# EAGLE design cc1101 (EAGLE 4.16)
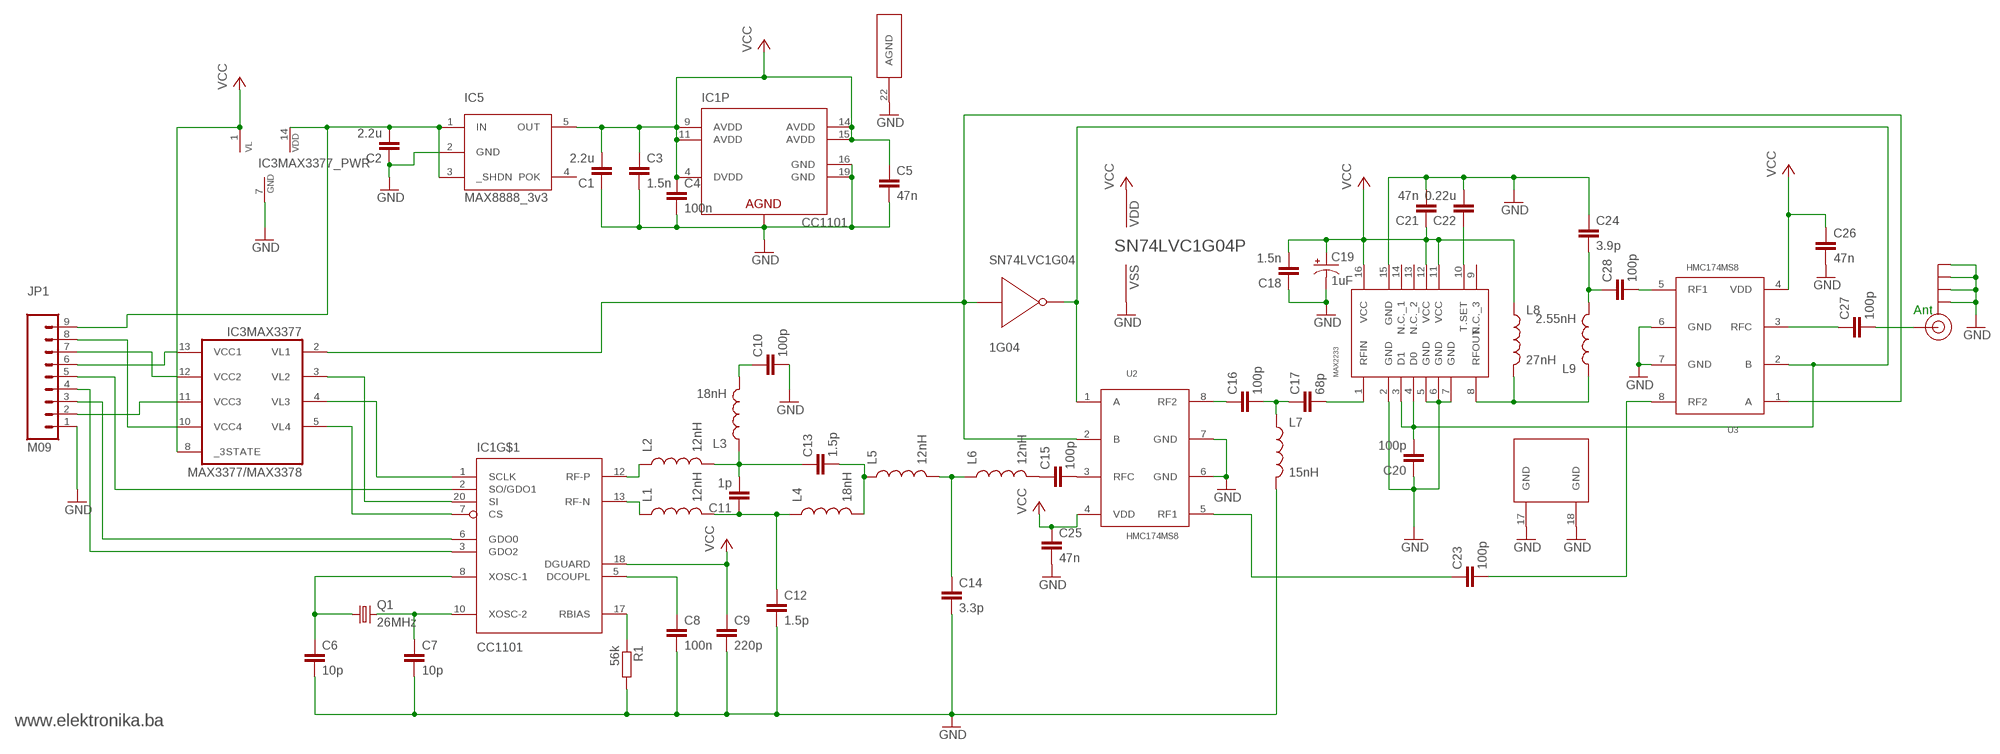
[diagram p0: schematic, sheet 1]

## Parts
C1  2.2u  C-EUC0603  [C0603]
C2  2.2u  C-EUC0603  [C0603]
C3  1.5n  C-EUC0603  [C0603]
C4  100n  C-EUC0603  [C0603]
C5  47n  C-EUC0603  [C0603]
C6  10p  C-EUC0603  [C0603]
C7  10p  C-EUC0603  [C0603]
C8  100n  C-EUC0603  [C0603]
C9  220p  C-EUC0603  [C0603]
C10  100p  C-EUC0603  [C0603]
C11  1p  C-EUC0603  [C0603]
C12  1.5p  C-EUC0603  [C0603]
C13  1.5p  C-EUC0603  [C0603]
C14  3.3p  C-EUC0603  [C0603]
C15  100p  C-EUC0603  [C0603]
C16  100p  C-EUC0603  [C0603]
C17  68p  C-EUC0603  [C0603]
C18  1.5n  C-EUC0603  [C0603]
C19  1uF  CAP_POL1206  [EIA3216]
C20  100p  C-EUC0603  [C0603]
C21  47n  C-EUC0603  [C0603]
C22  0.22u  C-EUC0603  [C0603]
C23  100p  C-EUC0603  [C0603]
C24  3.9p  C-EUC0603  [C0603]
C25  47n  C-EUC0603  [C0603]
C26  47n  C-EUC0603  [C0603]
C27  100p  C-EUC0603  [C0603]
C28  100p  C-EUC0603  [C0603]
IC1  CC1101  CC1100QLP-20-NEW  [QLP-20-NEW]
IC3  MAX3377/MAX3378  MAX3377  [TSSOP14]
IC5  MAX8888_3v3  MAX8888  [SOT23-5]
JP1  M09  [1X09]
L1  12nH  INDUCTOR0603  [0603]
L2  12nH  INDUCTOR0603  [0603]
L3  18nH  INDUCTOR0603  [0603]
L4  18nH  INDUCTOR0603  [0603]
L5  12nH  INDUCTOR0603  [0603]
L6  12nH  INDUCTOR0603  [0603]
L7  15nH  INDUCTOR0603  [0603]
L8  27nH  INDUCTOR0603  [0603]
L9  2.55nH  INDUCTOR0603  [0603]
Q1  26MHz  CRYSTAL5X3  [CRYSTAL-SMD-5X3]
R1  56k  R-EU_R0603  [R0603]
SMA1  SMA_EDGE  [SMA-EDGE]
SN74LVC1G04  1G04  [SOT23-5]
U2  HMC174MS8  [MSOP8]
U3  HMC174MS8  [MSOP8]
U$1  MAX2233TSSOP  MAX2233TSSOP16  [TSSOP16]

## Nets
DCOUPL: C8.1 IC1.5(DCOUPL)
GND: C1.1 C2.1 C3.2 C4.2 C5.2 C6.2 C7.2 C8.2 C9.2 C10.2 C12.2 C14.2 C18.1 C19.C(-) C20.1 C21.2 C22.2 C24.1 C25.2 C26.2 IC1.16(P:GND) IC1.19(P:GND) IC1.21(P:AGND) IC1.22(AGND) IC3.7(MAX3377_PWR:GND) IC5.2(GND) JP1.1 L7.2 R1.2 SMA1.GND@0(GND) SMA1.GND@1(GND) SMA1.GND@2(GND) SMA1.GND@3(GND) SN74LVC1G04.3(VSS) U2.6(GND) U2.7(GND) U3.6(GND) U3.7(GND) U$1.2(GND) U$1.5(GND) U$1.6(GND) U$1.7(GND) U$1.15(GND) U$1.17(GND) U$1.18(GND)
L8: IC1.12(RF-P) L2.1
N$1: IC1.17(RBIAS) R1.1
N$2: C15.1 L6.2
N$3: IC1.13(RF-N) L1.1
N$4: C10.1 L3.2
N$5: IC3.13(MAX3377:VCC1) JP1.6
N$6: C6.1 IC1.8(XOSC-1) Q1.1
N$7: C15.2 U2.3(RFC)
N$8: L8.2 L9.1 U$1.8(RFOUT)
N$9: C13.2 L4.2 L5.1
N$10: C7.1 IC1.10(XOSC-2) Q1.3
N$11: C16.1 U2.8(RF2)
N$12: C28.2 U3.5(RF1)
N$13: C27.1 U3.3(RFC)
N$14: C17.2 U$1.1(RFIN)
N$15: C20.2 SN74LVC1G04.4(Q) U2.1(A) U3.2(B) U$1.3(D1) U$1.4(D0)
N$16: C11.2 C13.1 L2.2 L3.1
N$18: C27.2 SMA1.SIG(SIGNAL)
N$19: C22.1 U$1.10(T.SET)
N$20: C24.2 C28.1 L9.2
N$21: C16.2 C17.1 L7.1
N$22: IC1.2(SO/GDO1) JP1.5
N$23: IC1.1(SCLK) IC3.4(MAX3377:VL3)
N$24: IC1.20(SI) IC3.3(MAX3377:VL2)
N$25: IC1.7(CS) IC3.5(MAX3377:VL4)
N$26: IC1.6(GDO0) JP1.3
N$27: IC1.3(GDO2) JP1.4
N$28: IC3.12(MAX3377:VCC2) JP1.7
N$29: C2.2 IC3.14(MAX3377_PWR:VDD) IC5.1(IN) IC5.3(_SHDN) JP1.9
N$30: C23.1 U2.5(RF1)
N$31: IC3.11(MAX3377:VCC3) JP1.2
N$32: C23.2 U3.8(RF2)
N$33: C11.1 C12.1 L1.2 L4.1
N$34: C14.1 L5.2 L6.1
N$36: IC3.10(MAX3377:VCC4) JP1.8
N$47: IC3.2(MAX3377:VL1) SN74LVC1G04.2(A) U2.2(B) U3.1(A)
VCC: C1.2 C3.1 C4.1 C5.1 C9.1 C18.2 C19.A(+) C21.1 C25.1 C26.1 IC1.4(P:DVDD) IC1.9(P:AVDD) IC1.11(P:AVDD) IC1.14(P:AVDD) IC1.15(P:AVDD) IC1.18(DGUARD) IC3.1(MAX3377_PWR:VL) IC3.8(MAX3377:_3STATE) IC5.5(OUT) L8.1 SN74LVC1G04.5(VDD) U2.4(VDD) U3.4(VDD) U$1.11(VCC) U$1.12(VCC) U$1.16(VCC)
Unconnected: IC5.4(POK) U$1.9(N.C._3) U$1.13(N.C._2) U$1.14(N.C._1)

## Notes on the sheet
- Ant
- www.elektronika.ba

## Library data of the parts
C1-C18 C20-C28 = rcl:C-EU: CAPACITOR, European symbol
C19 = SparkFun:CAP_POL: Capacitor Polarized
IC1 = chipcon-ti:CC1100: Single Chip Low Cost Low Power RF Transceiver 315/433/868 and 915 MHz ISM/SRD band systems
IC3 = MAX3377:MAX3377: Micropower PLL
IC5 = MAX3377:MAX8888
JP1 = SparkFun:M09: Header 9 Standard 9-pin 0.1" header. Use with straight break away headers (SKU : PRT-00116), right angle break away headers (PRT-00553), swiss pins (PRT-00743), machine pins (PRT-00117), and female headers (PRT-00115).
L1-L9 = SparkFun:INDUCTOR: Inductors
Q1 = SparkFun:CRYSTAL: Crystals
R1 = rcl:R-EU_: RESISTOR, European symbol
SMA1 = SparkFun:SMA_EDGE: SMA Antenna Connector End launch SMA connector. The paste layer has been removed so that the connector can be hand soldered onto the board after reflow.
SN74LVC1G04 = little-logic:1G04: NOT
U2 U3 = trax:HMC174MS8
U$1 = trax:MAX2233

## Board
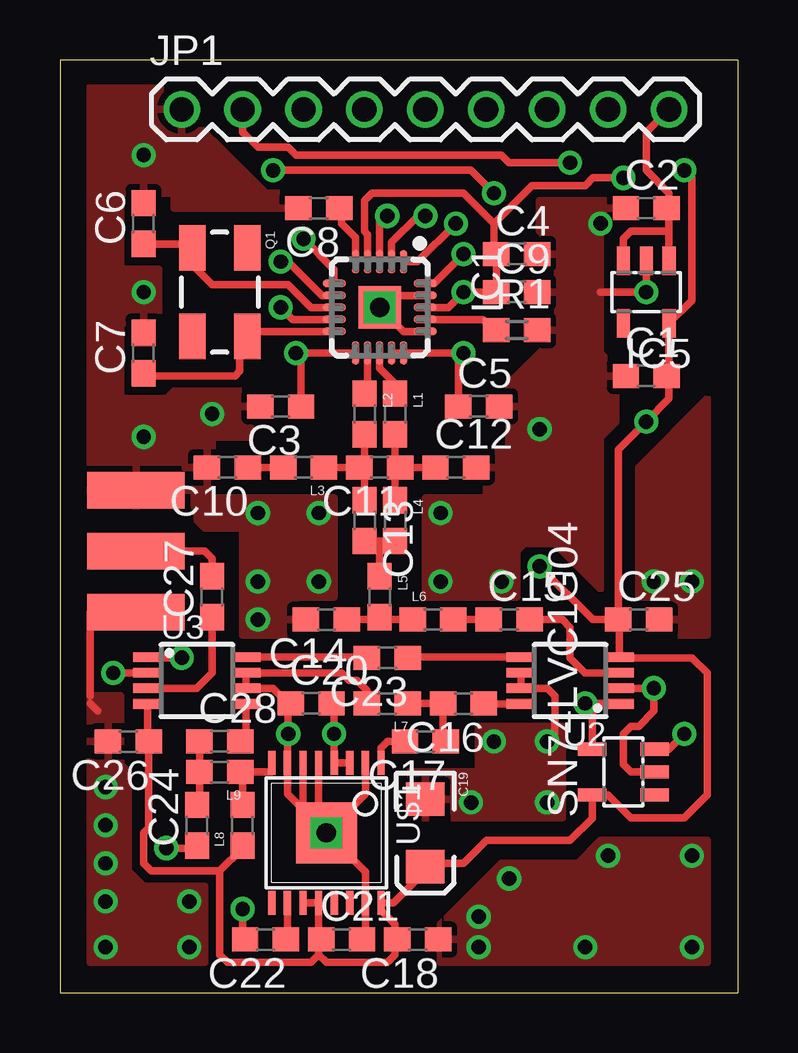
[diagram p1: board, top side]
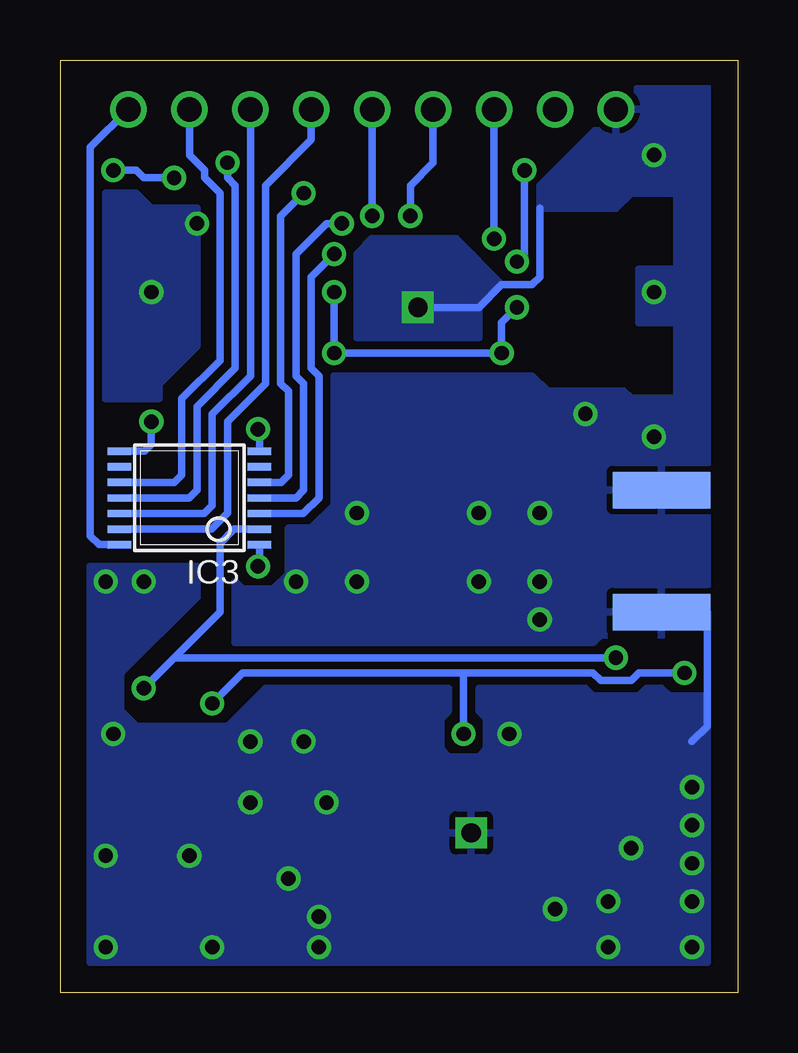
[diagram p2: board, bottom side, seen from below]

Size 28.25 x 38.88 mm. Coordinates in mm from the lower left corner, seen from the top.
Outline: 28.25,38.88 0,38.88 0,0 28.25,0 28.25,38.88
Copper layers (1*16): Top 0.035mm / dielectric 1.5mm / Bottom 0.035mm
Design rules "default": minimum track width 10mil, minimum drill 24mil, track to track 8mil, track to pad 8mil, pad to pad 8mil, via to via 8mil, smd to smd 8mil, copper to edge 40mil, drill to drill 8mil, minimum pad ring 10mil, minimum via ring 8mil, stop-mask expansion 4mil, vias tented up to drill 0mil, thermal gap 10mil

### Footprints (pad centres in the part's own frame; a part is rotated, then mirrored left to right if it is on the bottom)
C0603 = smd 1.1 x 1: 1 -0.85,0; 2 0.85,0
EIA3216 = smd 1.4 x 1.6: A 1.4,0; C -1.4,0
QLP-20-NEW = smd 0.95 x 0.3: 1 -1.9,1; 2 -1.9,0.5; 3 -1.9,0; 4 -1.9,-0.5; 5 -1.9,-1; 11 1.9,-1; 12 1.9,-0.5; 13 1.9,0; 14 1.9,0.5; 15 1.9,1 | smd 0.3 x 0.95: 6 -1,-1.9; 7 -0.5,-1.9; 8 0,-1.9; 9 0.5,-1.9; 10 1,-1.9; 16 1,1.9; 17 0.5,1.9; 18 0,1.9; 19 -0.5,1.9; 20 -1,1.9 | drill 0.8 square: 21 0,0 | smd 1.778 x 1.778: 22 0,0
TSSOP14 = smd 0.305 x 0.991: 1 -2.275,-2.918; 2 -1.625,-2.918; 3 -0.975,-2.918; 4 -0.325,-2.918; 5 0.325,-2.918; 6 0.975,-2.918; 7 1.625,-2.918; 8 1.625,2.918; 9 0.975,2.918; 10 0.325,2.918; 11 -0.325,2.918; 12 -0.975,2.918; 13 -1.625,2.918; 14 -2.275,2.918
SOT23-5 = smd 0.55 x 1.2: 1 -0.95,-1.3; 2 0,-1.3; 3 0.95,-1.3; 4 0.95,1.3; 5 -0.95,1.3
1X09 = drill 1.016 round: 1 0,0; 2 2.54,0; 3 5.08,0; 4 7.62,0; 5 10.16,0; 6 12.7,0; 7 15.24,0; 8 17.78,0; 9 20.32,0
0603 = smd 1.1 x 1: 1 -0.85,0; 2 0.85,0
CRYSTAL-SMD-5X3 = smd 1.9 x 1.1: 1 -1.85,-1.15; 2 1.85,-1.15; 3 1.85,1.15; 4 -1.85,1.15
R0603 = smd 1.1 x 1: 1 -0.85,0; 2 0.85,0
SMA-EDGE = smd 1.524 x 4.064: GND@0 0,0; GND@1 5.08,0; SIG 2.54,0 | smd 1.524 x 4.064 bottom: GND@2 0,0; GND@3 5.08,0
MSOP8 = smd 0.4 x 1.2: 1 -0.975,-2.05; 2 -0.325,-2.05; 3 0.325,-2.05; 4 0.975,-2.05; 5 0.975,2.05; 6 0.325,2.05; 7 -0.325,2.05; 8 -0.975,2.05
TSSOP16 = smd 0.305 x 0.991: 1 -2.275,-2.918; 2 -1.625,-2.918; 3 -0.975,-2.918; 4 -0.325,-2.918; 5 0.325,-2.918; 6 0.975,-2.918; 7 1.625,-2.918; 8 2.275,-2.918; 9 2.275,2.918; 10 1.625,2.918; 11 0.975,2.918; 12 0.325,2.918; 13 -0.325,2.918; 14 -0.975,2.918; 15 -1.625,2.918; 16 -2.275,2.918 | smd 2.54 x 2.54: 17 0,0 | drill 0.8 square: 18 0,0

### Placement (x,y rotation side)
C1  24.44,25.71 0 top
C2  24.44,32.7 0 top
C3  9.2,24.44 180 top
C4  19.05,30.79 0 top
C5  17.46,24.44 0 top
C6  3.49,32.06 90 top
C7  3.49,26.66 90 top
C8  10.79,32.7 180 top
C9  19.05,29.2 0 top
C10  6.98,21.9 180 top
C11  13.33,21.9 180 top
C12  16.51,21.9 0 top
C13  12.69,19.68 270 top
C14  11.11,15.55 180 top
C15  18.73,15.55 0 top
C16  16.82,12.06 180 top
C17  15.23,10.47 180 top
C18  14.92,2.22 180 top
C19  15.23,6.66 270 top
C20  10.47,12.06 0 top
C21  11.74,2.22 0 top
C22  8.57,2.22 180 top
C23  13.65,13.96 180 top
C24  5.71,6.98 90 top
C25  24.12,15.55 0 top
C26  2.85,10.47 180 top
C27  6.34,16.5 90 top
C28  6.66,10.47 0 top
IC1  13.33,28.57 270 top
IC3  22.86,20.95 90 bottom
IC5  24.44,29.2 180 top
JP1  5.08,36.82 0 top
L1  13.96,24.12 270 top
L2  12.69,24.12 270 top
L3  10.15,21.9 180 top
L4  13.96,19.68 270 top
L5  13.33,16.5 270 top
L6  15.55,15.55 0 top
L7  13.65,12.06 180 top
L8  7.62,6.98 90 top
L9  6.66,9.2 180 top
Q1  6.66,29.2 270 top
R1  19.05,27.62 0 top
SMA1  3.17,20.95 270 top
SN74LVC1G04  23.49,9.2 90 top
U2  21.27,13.01 90 top
U3  5.71,13.01 270 top
U$1  11.11,6.66 180 top
U$2  [ELEBALOGO_B_122]  15.87,20.63 0 bottom

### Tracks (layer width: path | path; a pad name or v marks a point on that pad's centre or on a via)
DCOUPL
  Top 0.305: IC1.5 12.33,31.47 11.74,32.06 11.74,32.7 C8.1
GND  (via drill 0.6)
  Top 0.305: C9.2 20,29.2 19.89,29.31 | 20,27.62 19.89,27.72 | U3.6 | U3.6 U3.7 7.62,13.34 7.62,13.33 11.74,13.33 12.06,13.01 12.38,13.01 12.8,12.59 L7.2 | U2.7 | U2.7 U2.6 | U2.7 19.05,12.69 | U3.6 8.88,12.69 9.52,12.06 | 9.52,12.06 C20.1 | 1.58,11.74 1.27,12.06 | 1.27,12.38 1.27,15.87 SMA1.GND@1 | IC5.2 v24.44,29.2 22.54,29.2 | 9.52,12.06 v9.52,10.79 9.48,10.79 U$1.7 9.48,8.29 10.15,7.61 | 10.79,7.61 10.78,7.61 | C24.1 5.71,6.03 v4.44,6.03 | C22.2 arc-90 7.62,2.32 v7.62,3.49 | C21.2 12.69,2.22 arc90 12.73,2.25 | 12.73,2.25 U$1.15 | U2.7 20.32,12.69 20.63,12.38 20.63,10.79 v20.32,10.47 | SN74LVC1G04.3 25.39,10.15 v26.03,10.79 | U$1.18 11.11,7.3 10.79,7.61 | 10.79,7.61 10.15,7.61 | 10.15,7.61 10.13,7.61 | U$1.6 10.13,7.64 10.15,7.61 | U$1.5 10.78,7.62 10.79,7.61 | U$1.2 12.73,8.29 U$1.18 | 12.73,2.25 12.73,5.04 U$1.18 | IC1.16 14.33,27.57 IC1.22 13.83,29.07 IC1.19
  Top 0.406: R1.2 20,27.62
  Bottom 0.305: SMA1.GND@1 1.27,15.87 1.27,11.11 1.9,10.47 | IC3.7 19.94,23.43 v20,23.49 | IC1.22 10.79,28.57 9.84,29.52 8.57,29.52 8.25,29.84 8.25,32.7
  other vias: 3.49,29.2 6.34,24.12 10.79,20 10.79,17.14 8.25,20 8.25,17.14 8.25,15.55 3.49,34.92 20.32,7.93 5.39,1.9 1.9,1.9 5.39,3.8 1.9,8.57 15.87,20 15.87,17.14 18.41,17.14 3.49,23.17 24.76,17.14 26.35,17.14 22.86,5.71 26.35,5.71 21.9,1.9 26.35,1.9 17.46,1.9 17.14,7.93 18.09,10.47 18.73,4.76 1.9,5.39 1.9,3.8 1.9,6.98 22.54,32.06 17.46,3.17
  pour Top: 1.27,37.78 1.27,20.31 5.71,20.31 5.71,19.68 6.03,19.36 7.62,19.36 7.62,14.92 9.84,14.92 9.84,16.5 11.42,16.5 11.42,20.63 6.34,20.63 6.34,23.17 7.93,23.17 7.93,25.08 4.76,25.08 4.44,24.76 2.54,24.76 2.54,27.93 4.12,27.93 4.12,30.16 2.54,30.16 2.54,33.33 4.76,33.33 4.76,32.7 9.52,32.7 9.52,33.33 8.57,33.33 4.12,37.78
  pour Bottom (no thermals): 15.87,30.79 15.23,31.43 11.74,31.43 9.84,29.52 10.79,28.57 10.79,27.3 15.87,27.3
  pour Bottom: 1.27,37.78 4.12,37.78 8.25,33.65 8.25,32.7 5.08,32.7 4.44,33.33 2.54,33.33 2.54,30.16 4.12,30.16 4.12,27.93 2.54,27.93 2.54,24.76 4.44,24.76 4.76,25.08 7.93,25.08 8.57,25.71 16.82,25.71 16.82,20.31 17.78,19.36 18.73,19.36 18.73,17.46 19.36,16.82 20.63,16.82 20.95,17.14 20.95,14.6 6.03,14.6 5.71,14.92 1.27,14.92
  pour Bottom: 1.27,1.26 26.98,1.26 26.98,17.77 22.54,17.77 22.54,16.5 25.71,13.33 25.71,11.74 25.08,11.11 21.27,11.11 19.68,12.69 12.06,12.69 12.06,11.74 12.38,11.42 12.38,10.15 12.06,9.84 10.79,9.84 10.47,10.15 10.47,11.42 10.79,11.74 10.79,12.69 6.34,12.69 6.03,12.38 4.12,12.38 3.81,12.69 3.17,12.69 2.85,12.38 1.27,12.38
  pour Top: 17.46,11.11 17.46,9.2 14.6,9.2 14.6,7.3 20.95,7.3 20.95,11.11
  pour Top: 6.03,1.26 6.03,4.44 3.49,4.44 2.85,5.07 2.85,9.2 2.54,9.52 2.54,12.38 1.27,12.38 1.27,1.26
  pour Top: 20,33.01 23.17,33.01 23.17,32.38 22.54,31.74 22.54,26.66 23.17,26.03 23.17,23.81 22.54,23.17 22.54,16.82 20.63,18.73 19.36,18.73 19.05,18.41 19.05,16.5 15.23,16.5 15.23,20.63 17.78,20.63 17.78,22.54 18.73,22.54 18.73,25.39 20.32,26.98 20.32,31.43 20,31.74
  pour Top: 24.12,21.9 26.98,24.76 26.98,14.92 25.39,14.92 25.39,16.5 24.12,16.5
  pour Top: 26.98,1.26 26.98,6.34 22.54,6.34 21.59,5.39 18.41,5.39 15.87,2.85 15.87,1.26
  pour Bottom: 22.54,32.7 24.44,32.7 25.08,33.33 26.35,33.33 26.35,24.76 24.12,24.76 24.12,25.39 22.54,26.98
L8
  Top 0.305: L2.1 12.69,25.08 12.83,25.21 IC1.12
N$1
  Top 0.305: R1.1 18.09,27.62 17.64,28.07 IC1.17
N$2
  Top 0.305: L6.2 C15.1
N$3
  Top 0.305: L1.1 13.96,25.39 13.33,26.03 IC1.13
N$4
  Top 0.305: L3.2 C10.1
N$5
  Bottom 0.305: IC3.13 21.94,19.32 21.27,20 21.27,23.81 19.68,25.39 19.68,33.65 17.78,35.55 JP1.6
N$6
  Top 0.305: IC1.8 10.47,28.57 9.52,29.52 6.34,29.52 5.39,30.47 5.39,31.11 | 5.39,31.11 5.39,31.05 Q1.1 | C6.1 5.39,31.21 5.39,31.11
N$7
  Top 0.305: U2.3 21.89,13.34 21.27,13.96 21.27,15.23 20.95,15.55 C15.2
N$8
  Top 0.305: U$1.8 8.83,9.2 7.62,9.2 | L9.1 7.62,9.2 | 7.62,9.2 L8.2
N$9
  Top 0.305: C13.2 12.69,18.73 12.8,18.83 13.33,18.83 | 13.33,18.83 L4.2 | L5.1 13.33,18.83
N$10
  Top 0.305: 7.5,27.5 7.62,27.62 7.66,27.57 IC1.10 | 7.5,27.5 Q1.3 | 7.5,27.5 7.5,25.91 7.3,25.71 3.49,25.71 C7.1
N$11
  Top 0.305: C16.1 17.78,12.06 17.8,12.04 U2.8
N$12
  Top 0.305: U3.5 7.76,10.47 C28.2
N$13
  Top 0.305: U3.3 5.7,12.69 6.34,13.33 C27.1
N$14
  Top 0.305: U$1.1 13.38,10.21 13.65,10.47 C17.2
N$15  (via drill 0.6)
  Top 0.305: U3.2 v2.22,13.34 v2.22,13.33 | U2.1 23.3,12.06 v21.9,12.06 22.19,11.77 SN74LVC1G04.4 | C20.2 11.42,12.06 v11.42,10.79 v11.43,10.78 U$1.4 12.06,9.58 | 12.06,9.58 U$1.3 | 12.06,9.58 12.06,9.52
  Bottom 0.305: v21.9,12.06 20.63,13.33 11.42,13.33 | v2.22,13.33 4.12,13.33 4.44,13.01 5.71,13.01 6.03,13.33 11.42,13.33 | 11.42,13.33 v11.42,10.79
N$16
  Top 0.305: 12.69,21.9 L2.2 | 12.69,21.9 C13.1 | 12.69,21.9 C11.2 | L3.1 12.69,21.9
N$18
  Top 0.305: C27.2 6.34,18.09 6.03,18.41 SMA1.SIG
N$19
  Top 0.305: C22.1 9.52,2.22 9.48,2.25 U$1.10
N$20
  Top 0.305: 5.71,10.47 C28.1 L9.2 5.81,7.61 5.71,7.61 C24.2
N$21
  Top 0.305: 15.87,12.06 C16.2 | 15.87,12.06 15.97,11.96 15.97,10.69 16.19,10.47 C17.1 | L7.1 15.87,12.06
N$22  (via drill 0.6)
  Top 0.305: IC1.2 13.83,31.29 14.92,32.38 v15.23,32.38
  Bottom 0.305: v15.23,32.38 JP1.5
N$23  (via drill 0.6)
  Top 0.305: IC1.1 14.91,30.47 v16.51,32.06
  Bottom 0.305: IC3.4 18.42,20.62 18.09,20.95 18.09,25.39 18.41,25.71 18.41,30.79 17.14,32.06 v16.51,32.06
N$24  (via drill 0.6)
  Top 0.305: IC1.20 15.6,29.57 v16.82,30.79
  Bottom 0.305: IC3.3 18.12,19.97 17.46,20.63 17.46,25.71 17.78,26.03 17.78,29.84 v16.82,30.79
N$25  (via drill 0.6)
  Top 0.305: IC1.7 10.92,29.07 9.52,30.47 v9.2,30.47 | v8.88,34.28 17.14,34.28 v18.09,33.33
  Bottom 0.305: v9.2,30.47 8.88,30.79 v8.88,34.28 | IC3.5 19.04,21.27 18.73,21.58 18.73,25.08 19.05,25.39 19.05,32.38 v18.09,33.33
N$26  (via drill 0.6)
  Top 0.305: IC1.6 11.43,30.15 v10.15,31.43
  Bottom 0.305: v10.15,31.43 JP1.3
N$27  (via drill 0.6)
  Top 0.305: IC1.3 13.33,32.06 v13.65,32.38
  Bottom 0.305: v13.65,32.38 13.65,33.65 12.69,34.6 JP1.4
N$28
  Bottom 0.305: IC3.12 22.24,19.97 21.9,20.31 21.9,24.12 20.32,25.71 JP1.7
N$29
  Top 0.305: IC5.3 23.49,31.43 23.81,31.74 25.39,31.74 | 25.39,31.74 25.39,32.7 25.39,33.33 24.44,34.28 24.44,35.87 JP1.9 | IC5.1 25.39,31.74
  Top 0.406: 25.39,32.7 C2.2
  Bottom 0.305: IC3.14 26.61,18.67 26.98,19.04 26.98,35.24 JP1.9
N$30
  Top 0.305: C23.1 14.28,13.96 14.28,13.99 U2.5
N$31  (via drill 0.6)
  Top 0.305: JP1.2 7.62,35.87 8.25,35.24 9.52,35.24 9.84,34.92 18.41,34.92 18.73,34.6 v21.27,34.6
  Bottom 0.305: IC3.11 22.86,20.62 22.54,20.95 22.54,24.44 20.95,26.03 20.95,33.65 21.27,33.97 v21.27,34.6
N$32
  Top 0.305: C23.2 13.01,13.96 13.01,13.99 U3.8
N$33
  Top 0.305: 13.96,21.9 L1.2 | C12.1 C11.1 13.96,21.9 | L4.1 13.96,21.9
N$34
  Top 0.305: C14.1 13.33,15.55 | 13.33,15.55 L5.2 | 13.33,15.55 L6.1
N$36
  Bottom 0.305: IC3.10 23.48,21.27 23.17,21.58 23.17,24.76 21.59,26.35 21.59,33.33 22.22,33.97 22.22,34.28 22.86,34.92 JP1.8
N$47  (via drill 0.6)
  Top 0.305: U3.1 3.68,13.96 v5.08,13.96 | U2.2 v24.76,12.69 24.76,11.74 24.12,11.11 23.81,11.11 23.49,10.79 23.49,9.52 23.81,9.2 SN74LVC1G04.2
  Bottom 0.305: v5.08,13.96 23.49,13.96 v24.76,12.69 21.59,15.87 21.59,18.73 20.99,19.32 IC3.2
VCC  (via drill 0.6)
  Top 0.305: IC1.14 14.28,26.67 14.28,26.66 14.29,26.67 IC1.15 v16.82,26.67 v16.82,26.66 16.61,26.45 C5.1 | IC1.9 9.7,28.07 v9.2,28.57 | IC1.18 16.19,28.57 v16.82,29.2 18.09,29.2 | IC1.11 v9.84,26.67 v9.84,26.66 10.05,26.45 C3.1 | IC1.4 12.83,31.61 12.69,31.74 12.69,33.01 13.01,33.33 16.82,33.33 18.09,32.06 | C4.1 18.09,30.79 | U3.4 3.66,10.62 3.81,10.47 C26.1 3.7,6.88 3.49,6.66 3.49,5.39 3.81,5.07 6.66,5.07 | C25.1 23.49,15.55 23.32,15.38 U2.4 23.47,13.99 23.49,13.96 26.35,13.96 26.98,13.33 26.98,8.25 26.03,7.3 23.81,7.3 22.85,8.25 SN74LVC1G04.5 | 22.22,8.25 SN74LVC1G04.5 | C25.1 23.28,22.64 v24.44,23.81 25.39,24.76 25.39,25.39 | 25.39,25.39 25.39,25.71 C1.2 25.29,25.5 25.39,25.39 | 25.39,25.39 25.39,25.4 IC5.5 26.35,28.86 26.35,33.97 v26.03,34.28 | C25.1 22.22,15.55 v20,17.77 | 18.09,29.2 C9.1 | C4.1 18.2,29.31 18.09,29.2 | C4.1 18.09,30.89 18.09,32.06 | v23.49,33.97 22.22,33.97 21.9,33.65 19.68,33.65 18.09,32.06 | 10.79,2.22 C21.1 | 10.79,2.22 10.78,2.22 U$1.12 10.15,3.74 | 10.15,3.74 U$1.11 | 10.15,3.74 10.15,3.8 | SN74LVC1G04.5 22.19,7.27 21.27,6.34 17.78,6.34 16.82,5.39 15.23,5.39 C19.A 15.23,5.07 13.9,3.74 U$1.16 13.38,3.43 13.96,2.85 13.96,2.22 | 13.96,2.22 C18.2 | 13.96,2.22 13.96,1.58 13.65,1.26 11.11,1.26 10.79,1.58 | 10.79,1.58 10.79,2.22 | 10.79,1.58 10.47,1.26 6.98,1.26 6.66,1.58 6.66,5.07 | L8.1 7.62,6.03 6.66,5.07
  Bottom 0.305: v9.2,28.57 9.84,27.93 v9.84,26.66 v16.82,26.66 v16.82,29.2 | IC3.1 19.94,17.83 v20,17.77 | v23.49,33.97 24.76,33.97 25.08,34.28 v26.03,34.28 | IC3.8 24.72,22.57 24.44,22.85 v24.44,23.81

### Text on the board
_tsilk: 1 | 2 | 3 | 4 | 5 | 6 | 7 | 8 | 9 | www.elektronika.ba | CC1101 | 250mW
_bsilk: GND | SCLK | GD2 | SO | PA | SI | CS | + | GD0 | __ | __ | v2.0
